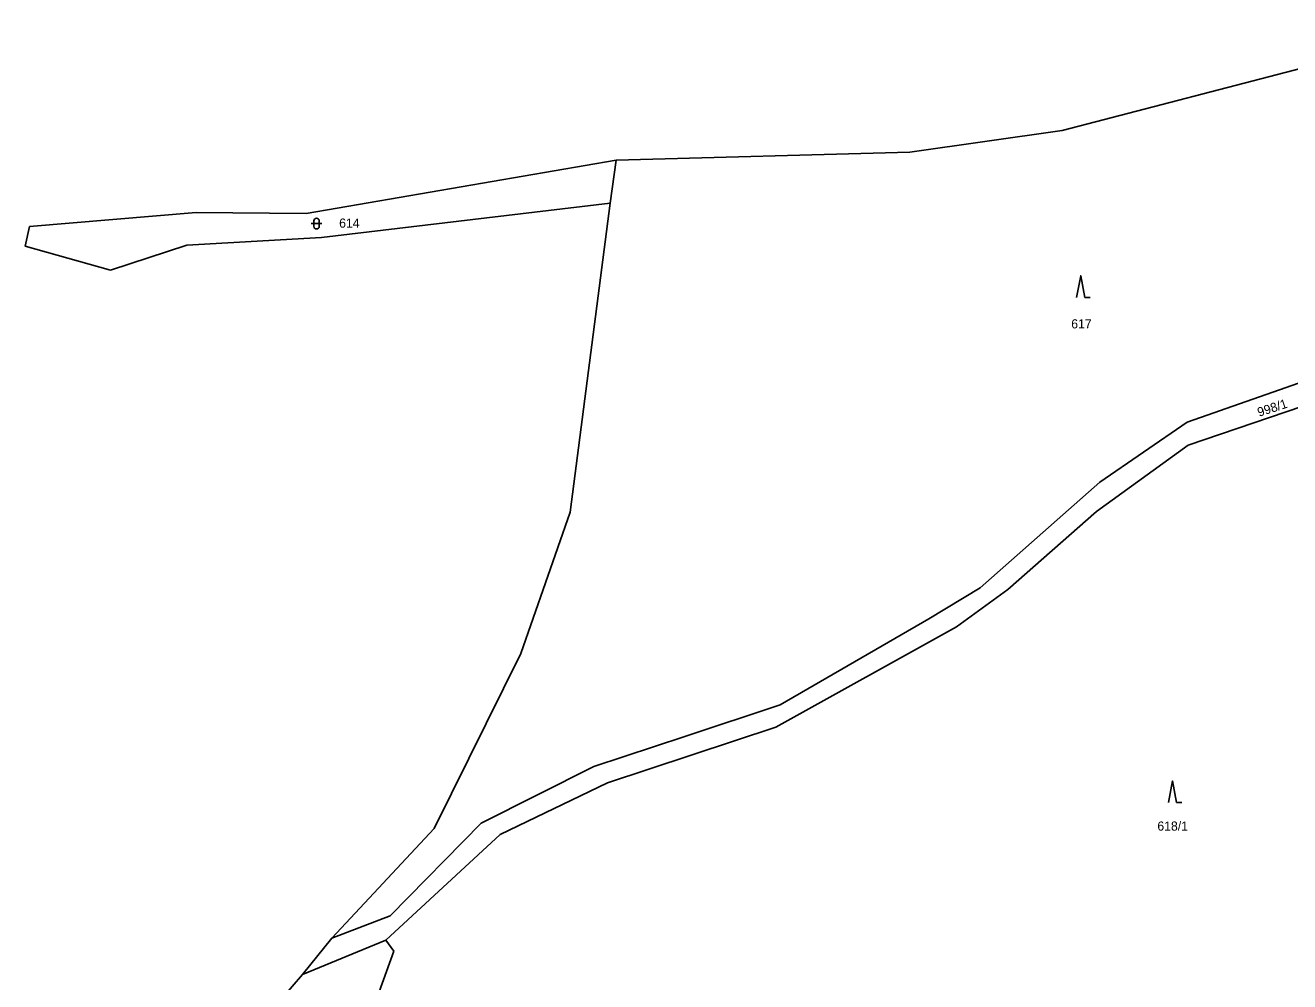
# Model space of a CAD drawing. Extents: x -754970 to -752637, y -970569 to -968179.
# Drawn here: x -754426 to -754191, y -969415.7 to -969237.9 of the extents above; entities that cross this region are included whole.
import ezdxf
from ezdxf.enums import TextEntityAlignment as Align

# ---------------------------------------------------------------- set-up
doc = ezdxf.new("R2010")
doc.units = 0
doc.header["$LTSCALE"] = 0.68
doc.layers.add('1', color=7, linetype='Continuous', lineweight=25)
doc.layers.add('3', color=7, linetype='Continuous', lineweight=25)
doc.layers.add('2', color=7, linetype='Continuous')

msp = doc.modelspace()

# ---------------------------------------------------------------- linework, layer by layer
at = {"layer": '1'}
for p, q in [((-754233.28, -969257.41), (-754158.25, -969237.86)), ((-754261.6, -969261.45), (-754233.28, -969257.41)), ((-754316.16, -969262.94), (-754373.79, -969272.84)), ((-754316.16, -969262.94), (-754317.28, -969270.93)), ((-754316.16, -969262.94), (-754261.6, -969261.45)), ((-754317.28, -969270.93), (-754370.92, -969277.31)), ((-754317.28, -969270.93), (-754324.73, -969328.38)), ((-754394.23, -969272.68), (-754425.2, -969275.24)), ((-754373.79, -969272.84), (-754394.23, -969272.68)), ((-754425.2, -969275.24), (-754426, -969278.91)), ((-754426, -969278.91), (-754410.19, -969283.38)), ((-754410.19, -969283.38), (-754395.98, -969278.75)), ((-754395.98, -969278.75), (-754370.92, -969277.31)), ((-754210, -969311.64), (-754181.26, -969301.58)), ((-754180.3, -969305.89), (-754209.84, -969315.95)), ((-754210, -969311.64), (-754226.29, -969322.82)), ((-754226.9, -969328.27), (-754209.84, -969315.95)), ((-754226.29, -969322.82), (-754248.48, -969342.46)), ((-754324.73, -969328.38), (-754333.87, -969354.66)), ((-754243.37, -969342.78), (-754226.9, -969328.27)), ((-754248.48, -969342.46), (-754258.06, -969348.21)), ((-754252.88, -969349.68), (-754243.37, -969342.78)), ((-754286.48, -969368.34), (-754252.88, -969349.68)), ((-754258.06, -969348.21), (-754285.68, -969364.18)), ((-754333.87, -969354.66), (-754350.02, -969387.17)), ((-754303.4, -969370.09), (-754285.68, -969364.18)), ((-754317.77, -969378.72), (-754286.48, -969368.34)), ((-754320.33, -969375.68), (-754303.4, -969370.09)), ((-754341.24, -969386.21), (-754320.33, -969375.68)), ((-754337.73, -969388.29), (-754317.77, -969378.72)), ((-754358.16, -969403.46), (-754341.24, -969386.21)), ((-754358.96, -969407.93), (-754337.73, -969388.29)), ((-754369.02, -969407.61), (-754374.45, -969414.32)), ((-754374.45, -969414.32), (-754358.96, -969407.93)), ((-754357.52, -969410.01), (-754358.96, -969407.93)), ((-754360.25, -969417.54), (-754357.52, -969410.01)), ((-754374.45, -969414.32), (-754419.47, -969466.57))]:
    msp.add_line(p, q, dxfattribs=at)
msp.add_lwpolyline([(-754350.02, -969387.17), (-754369.02, -969407.61), (-754358.16, -969403.46)], dxfattribs=at)
at = {"layer": '3'}
for p, q in [((-754372.861, -969274.731), (-754370.859, -969274.731)), ((-754372.361, -969274.231), (-754372.361, -969275.232)), ((-754371.359, -969275.232), (-754371.359, -969274.231)), ((-754229.07, -969288.44), (-754228.074, -969288.44)), ((-754211.99, -969382.35), (-754210.994, -969382.35))]:
    msp.add_line(p, q, dxfattribs=at)
for points in [[(-754229.07, -969288.44), (-754229.82, -969284.44), (-754230.57, -969288.44)], [(-754211.99, -969382.35), (-754212.74, -969378.35), (-754213.49, -969382.35)]]:
    msp.add_lwpolyline(points, dxfattribs=at)
for centre, start, end in [((-754371.86, -969274.2309), 0, 180), ((-754371.86, -969275.2309), 180, 359.98789)]:
    msp.add_arc(centre, 0.5, start, end, dxfattribs=at)

# ---------------------------------------------------------------- texts
at = {"layer": '2'}
for s, p in [('614', (-754365.759, -969275.485)), ('617', (-754229.679, -969294.215)), ('618/1', (-754212.72, -969387.595))]:
    msp.add_text(s, height=1.7, dxfattribs=at).set_placement(p, align=Align.CENTER)
msp.add_text('998/1', height=1.7, rotation=18, dxfattribs=at).set_placement((-754193.9537, -969309.79), align=Align.CENTER)

doc.saveas('drawing.dxf')
